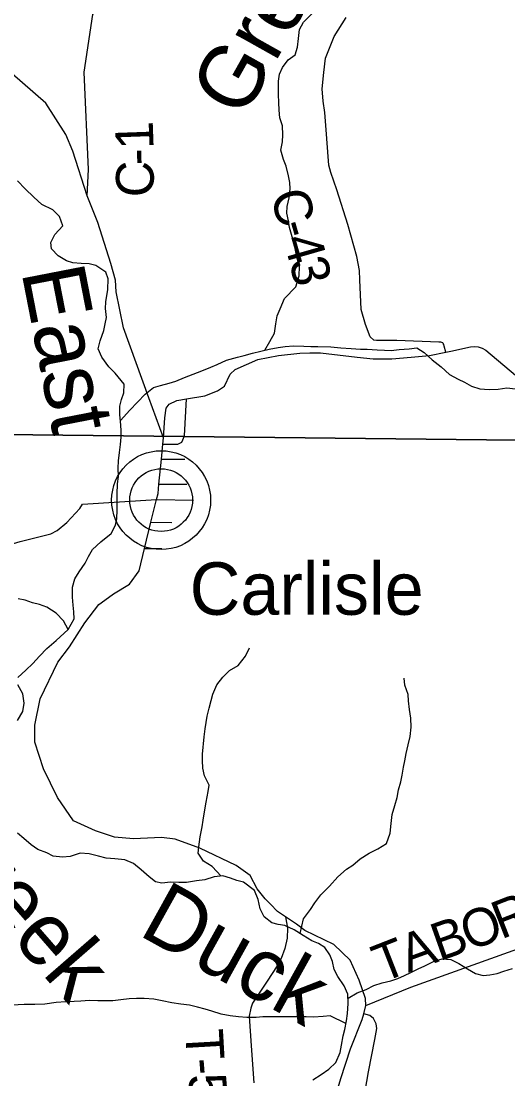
# Model space of a CAD drawing. Extents: x 2043100 to 2470832, y 443715 to 810583.
# Drawn here: x 2286943 to 2290807, y 633122 to 641526 of the extents above; entities that cross this region are included whole.
import ezdxf

# ---------------------------------------------------------------- set-up
doc = ezdxf.new("R2010")
doc.units = 0
for name, color, linetype in [('GM_X_County_Road', 7, 'Continuous'), ('GM_X_County_Road_Text', 7, 'Continuous'), ('GM_X_Major_River', 7, 'Continuous'), ('GM_X_Major_River_Text', 7, 'Continuous'), ('GM_X_Minor_River', 7, 'Continuous'), ('GM_X_Minor_River_Text', 7, 'Continuous'), ('GM_X_Section', 7, 'Continuous'), ('GM_X_State_Route', 7, 'Continuous'), ('GM_X_Township_Road', 7, 'Continuous'), ('GM_X_Township_Road_Text', 7, 'Continuous'), ('GM_X_Township_Subdivision', 7, 'Continuous'), ('GM_X_Unincorporated', 7, 'Continuous'), ('GM_X_Unincorporated_Location', 7, 'Continuous'), ('GM_X_Unincorporated_Text', 7, 'Continuous')]:
    doc.layers.add(name, color=color, linetype=linetype)

msp = doc.modelspace()

# ---------------------------------------------------------------- linework, layer by layer
at = {"layer": 'GM_X_County_Road'}
for points in [[(2287466.2, 640137.7), (2287478.1, 640348.3), (2287444.9, 641121.5), (2287511.6, 641579.3), (2287647.1, 641799.3), (2287668.6, 641842.4)], [(2290315.1, 638896), (2290303, 638942.6), (2290298.3, 638958), (2290294.8, 638964.9), (2290290, 638969.5), (2290282.8, 638972.7), (2290275.2, 638974.5), (2290260.4, 638976), (2289926.2, 638988.4), (2289764.2, 638987.8), (2289744.2, 638991.4), (2289713.7, 639017), (2289676, 639116.5), (2289644, 639234.2), (2289633.4, 639471.7), (2289630.6, 639543.8), (2289607.2, 639655.8), (2289536.2, 639911.5), (2289448.9, 640187), (2289401.3, 640324.7), (2289386.6, 640380.7), (2289379.8, 640450.7), (2289367.7, 640627), (2289355.6, 640801.2), (2289340.6, 640889.2), (2289333.4, 640987.3), (2289345.9, 641117.7), (2289360.5, 641232.1), (2289428.6, 641403.3), (2289522.8, 641554.7)], [(2286710.7, 637324.8), (2286935.8, 637392.2), (2287178.7, 637452.3), (2287230.3, 637479.2), (2287307.2, 637542.6), (2287409.3, 637652.5), (2287430.7, 637686.9), (2288018.2, 637726.2)], [(2289678.9, 633705.8), (2290037.4, 633851.3), (2290990.2, 634192.5)]]:
    msp.add_lwpolyline(points, dxfattribs=at)
at = {"layer": 'GM_X_Major_River'}
for points in [[(2286916.9, 636311.9), (2286980.4, 636370.4), (2287036, 636422.8), (2287089.5, 636481.2), (2287147.1, 636541.7), (2287222.6, 636604.2), (2287315.9, 636692.9)], [(2286915.3, 635969.5), (2286956.7, 636039.9), (2286968.2, 636108), (2286955.8, 636180), (2286917.3, 636251.9)], [(2289324.7, 633155.5), (2289386.4, 633198), (2289441.9, 633252.4), (2289475.3, 633330.7), (2289486.9, 633388.8), (2289500.4, 633463), (2289512, 633515.2), (2289525.5, 633583.3), (2289533.1, 633641.4), (2289538.6, 633719.6), (2289538.1, 633793.7), (2289507.6, 633861.5), (2289457.1, 633935.3), (2289428.8, 633991.2), (2289414.3, 634055.2), (2289394, 634107.1), (2289353.6, 634166.9), (2289303.5, 634196.6), (2289251.4, 634218.3), (2289183.1, 634261.9), (2289110.9, 634305.5), (2289036.7, 634341.1), (2288984.7, 634348.8), (2288932.6, 634362.5), (2288872.4, 634408.1), (2288842, 634472), (2288825.5, 634546), (2288795, 634617.9), (2288708.6, 634685.4), (2288654.6, 634699.1), (2288604.5, 634716.8), (2288544.4, 634734.4), (2288474.5, 634726), (2288402.7, 634703.5), (2288334.9, 634695.1), (2288255, 634682.5), (2288195.1, 634682.2), (2288129.1, 634683.7), (2288059.2, 634677.3), (2288009.2, 634687), (2287959, 634726.7), (2287896.7, 634782.4), (2287836.3, 634834), (2287766.2, 634861.6), (2287688.2, 634871.2), (2287618.2, 634876.7), (2287556.2, 634890.3), (2287484.1, 634909.9), (2287412.2, 634915.4), (2287332.4, 634888.9), (2287270.5, 634882.5), (2287198.5, 634892), (2287146.4, 634917.7), (2287076.3, 634945.3), (2287024.1, 634981), (2286965.7, 635032.7), (2286913.5, 635074.4)], [(2289259, 633115.1), (2289324.7, 633155.5)]]:
    msp.add_lwpolyline(points, dxfattribs=at)
at = {"layer": 'GM_X_Minor_River'}
for points in [[(2289124.6, 639414.1), (2289149.9, 639501.4), (2289153.5, 639575.5), (2289133, 639651.5), (2289122.7, 639707.5), (2289110.4, 639761.5), (2289094.1, 639813.5), (2289073.7, 639887.5), (2289065.4, 639939.5), (2289053.1, 639999.6), (2289054.7, 640053.7), (2289070.3, 640121.8), (2289079.9, 640194), (2289075.6, 640244), (2289065.3, 640298.1), (2289046.9, 640374.1), (2289026.6, 640428), (2289006.2, 640500), (2289017.8, 640566.2), (2289021.4, 640622.3), (2289017, 640694.4), (2288996.7, 640758.3), (2288992.3, 640818.4), (2288990, 640878.5), (2288985.6, 640942.5), (2288987.3, 640996.6), (2288987, 641048.7), (2288994.6, 641104.8), (2289018.3, 641157), (2289063.9, 641219.4), (2289117.6, 641259.8), (2289137.3, 641320), (2289144.9, 641388.1), (2289154.4, 641460.3), (2289184.1, 641518.6), (2289265.6, 641597.2)], [(2287631.8, 639394.5), (2287633.2, 639478.4), (2287616.9, 639532.3), (2287536.6, 639585.9), (2287482.6, 639597.7), (2287418.7, 639599.3), (2287354.7, 639606.9), (2287304.6, 639622.6), (2287236.4, 639660.3), (2287184.2, 639716), (2287179.9, 639766.1), (2287209.5, 639830.4), (2287273, 639900.8), (2287248.6, 639972.8), (2287194.3, 640026.6), (2287108.2, 640068.1), (2287043.9, 640127.8), (2286975.5, 640193.5), (2286915.2, 640257.2)], [(2287315.9, 636692.9), (2287363.2, 636777.3), (2287360.8, 636833.4), (2287356.5, 636885.4), (2287350, 636949.5), (2287351.5, 637029.6), (2287369, 637095.8), (2287402.6, 637150), (2287452.1, 637220.4), (2287477.7, 637272.7), (2287509.3, 637326.9), (2287576.8, 637389.4), (2287658.2, 637456), (2287691.7, 637522.3), (2287703.4, 637572.5), (2287706.9, 637642.6), (2287704.4, 637712.6), (2287706, 637766.7), (2287709.5, 637848.8), (2287715, 637908.9), (2287712.6, 637975), (2287716.2, 638033.1), (2287723.7, 638099.2), (2287731.3, 638161.3), (2287736.9, 638219.4), (2287736.5, 638277.5), (2287732, 638347.6), (2287725.6, 638397.6), (2287727.1, 638465.7), (2287740.8, 638519.8), (2287758.4, 638574), (2287761.9, 638642.1), (2287689.3, 638729.8), (2287639, 638779.5), (2287584.6, 638855.2), (2287554.1, 638923.1), (2287569.7, 638985.3), (2287599.1, 639067.6), (2287610.7, 639121.7), (2287620.3, 639171.8), (2287613.8, 639241.9), (2287615.5, 639296), (2287631.8, 639394.5)], [(2288877.9, 638911.3), (2288916.5, 638979.9), (2288956, 639046.2), (2288965.5, 639120.4), (2288975, 639184.5), (2288998.6, 639240.7), (2289034, 639323), (2289124.6, 639414.1)], [(2287731.1, 638354), (2287805.3, 638436.2), (2287866.8, 638498.6), (2287928.3, 638563.1), (2287993.9, 638615.6), (2288049.7, 638629.9), (2288119.5, 638648.4), (2288171.4, 638664.8), (2288239.1, 638695.2), (2288378.6, 638748.2), (2288448.3, 638776.7), (2288500.1, 638799), (2288573.8, 638831.5), (2288661.6, 638856.1), (2288713.4, 638870.4), (2288781.3, 638886.9), (2288845.1, 638903.3), (2288912.9, 638919.8), (2288982.8, 638932.2), (2289040.7, 638940.6), (2289106.5, 638947.1), (2289188.5, 638943.6), (2289242.5, 638941.9), (2289298.4, 638942.3), (2289402.3, 638938.9), (2289480.3, 638931.4), (2289562.3, 638925.9), (2289638.3, 638920.4), (2289690.2, 638920.7), (2289770.2, 638913.2), (2289828.1, 638911.6), (2289880.1, 638909.9), (2289944, 638916.4), (2290023.9, 638922.9), (2290085.8, 638929.3), (2290142, 638893.6), (2290206.3, 638835.9), (2290276.7, 638778.3), (2290345, 638718.7), (2290413.2, 638681.1), (2290463.3, 638657.4), (2290519.5, 638625.7), (2290585.6, 638604.1), (2290659.6, 638598.5), (2290729.5, 638603), (2290799.4, 638611.4), (2290867.3, 638605.9)], [(2287315.9, 636692.9), (2287279.4, 636760.8), (2287221.1, 636822.5), (2287146.8, 636870.1), (2287088.7, 636889.7), (2287034.6, 636905.4), (2286974.6, 636925), (2286918.5, 636936.7)], [(2288530.4, 634732.8), (2288460, 634808), (2288391.7, 634851.6), (2288349.3, 634915.4), (2288353, 634965.5), (2288364.4, 635045.7), (2288379.8, 635123.9), (2288389.5, 635178), (2288400.9, 635260.2), (2288412.4, 635320.3), (2288427.8, 635404.5), (2288435.5, 635454.6), (2288399, 635530.5), (2288384.6, 635590.4), (2288384.2, 635650.5), (2288383.8, 635700.6), (2288396.8, 635840.8), (2288404.4, 635902.9), (2288419.7, 636003.2), (2288437.2, 636067.4), (2288450.8, 636127.5), (2288464.4, 636179.7), (2288497.9, 636254), (2288543.4, 636314.3), (2288597, 636366.7), (2288666.6, 636407.2), (2288724.1, 636479.7), (2288755.6, 636548)], [(2289157.8, 634277.2), (2289184.2, 634394.1), (2289241.6, 634466.6), (2289275.2, 634520.8), (2289322.7, 634585.2), (2289390.2, 634651.8), (2289457.6, 634728.3), (2289525.1, 634788.8), (2289576.9, 634819.1), (2289634.5, 634869.6), (2289706.1, 634914.1), (2289775.8, 634948.6), (2289843.4, 634993), (2289872.8, 635073.3), (2289880.3, 635151.5), (2289889.8, 635223.6), (2289911.3, 635293.8), (2289928.8, 635358), (2289938.4, 635418.2), (2289957.9, 635482.4), (2289967.5, 635534.5), (2289979.1, 635598.6), (2289988.7, 635648.8), (2290000.3, 635706.9), (2290015.8, 635775.1), (2290031.3, 635841.3), (2290040.8, 635915.4), (2290036.3, 635987.5), (2290025.9, 636055.5), (2290019.4, 636125.5), (2290015, 636175.5), (2289988.5, 636249.5), (2289984.2, 636305.5)], [(2289538.3, 633763.6), (2289611.9, 633806.2), (2289681.7, 633830.6), (2289743.4, 633863), (2289809.2, 633885.5), (2289877, 633901.9), (2289932.8, 633918.3), (2289986.6, 633942.7), (2290038.4, 633967.1), (2290096.2, 633995.5), (2290147.9, 634019.8), (2290221.6, 634056.3), (2290285.4, 634074.8), (2290353.4, 634071.2), (2290417.6, 634037.6), (2290487.8, 633996), (2290550, 633958.3), (2290612.1, 633942.7), (2290664, 633949), (2290723.8, 633959.4), (2290775.7, 633977.8), (2290845.5, 633998.2)], [(2289521.3, 633562.1), (2289395.4, 633622.5), (2289341.5, 633618.2), (2289265.6, 633611.7), (2289205.6, 633615.3), (2288937.9, 633613.6), (2288861.9, 633615.1), (2288808, 633608.8), (2288734.1, 633608.3), (2288670.1, 633613.9), (2288602.1, 633623.5), (2288532.1, 633637), (2288458, 633658.6), (2288403.9, 633676.3), (2288343.8, 633691.9), (2288279.8, 633707.5), (2288211.8, 633715.1), (2288139.8, 633726.7), (2288061.7, 633742.2), (2287997.7, 633753.8), (2287919.7, 633761.3), (2287857.8, 633760.9), (2287801.9, 633758.5), (2287734, 633750.1), (2287670.1, 633741.7), (2287552.2, 633740.9), (2287486.2, 633744.5), (2287418.4, 633738.1), (2287364.4, 633735.7), (2287298.5, 633733.3), (2287220.6, 633728.8), (2287130.8, 633716.2), (2287050.9, 633711.7), (2286966.9, 633713.2), (2286871.1, 633708.5)]]:
    msp.add_lwpolyline(points, dxfattribs=at)
at = {"layer": 'GM_X_Section'}
for points in [[(2285494.3, 643590.2), (2290933.2, 643557.7), (2290892.7, 640243.7), (2290879.4, 638197.4), (2285590.3, 638253.8), (2285414.2, 638253.5)], [(2290879.4, 638197.4), (2290879.2, 634869.9), (2290878.9, 632765), (2285559.9, 632813), (2285590.3, 638253.8)]]:
    msp.add_lwpolyline(points, close=True, dxfattribs=at)
at = {"layer": 'GM_X_State_Route'}
for points in [[(2287957.9, 638532.1), (2287755.8, 639089.2), (2287696.8, 639374.8), (2287692.5, 639469), (2287654.8, 639601.1), (2287551.1, 639926.3), (2287466.2, 640137.7), (2287352.3, 640493.1), (2287299.3, 640624.8), (2287139.7, 640875.5), (2285633.9, 642188.3)], [(2288072.7, 638215.3), (2288083.1, 638375.1), (2288095.5, 638451.6), (2288119, 638483.6), (2288180.5, 638510.7), (2288257.3, 638526.1), (2288402.2, 638550.1), (2288503.1, 638588.2), (2288556.5, 638625.1), (2288602.9, 638720), (2288642.2, 638758.7), (2288821.2, 638837.4), (2288986.1, 638869.8), (2289156.3, 638887.3), (2289236.2, 638891.6), (2289319.2, 638889.6), (2289610.5, 638855), (2289739.2, 638843.9), (2289886.4, 638842.2), (2290039.6, 638856), (2290184.2, 638868.5), (2290315.1, 638896), (2290355.3, 638904.5), (2290511, 638937.7), (2290541.5, 638939.9), (2290571.8, 638937.1), (2290604.4, 638927.7), (2290633.8, 638912.1), (2290868.6, 638713.2)], [(2288072.7, 638215.3), (2287957.9, 638532.1)], [(2287665, 636968), (2287677.3, 636976.7), (2287804, 637053.5), (2287880, 637157.3), (2287921.5, 637334.8), (2287973.2, 637544.3), (2288018.2, 637726.2), (2288030, 637774.1), (2288037, 637846.3), (2288056.3, 638045.4), (2288068, 638166.2), (2288072.7, 638215.3)], [(2288922.2, 634509.7), (2288880.6, 634551.6), (2288816.8, 634630.6), (2288760.4, 634737.8), (2288650.5, 634817.8), (2288363, 634954.4), (2288167, 635026.7), (2288058.5, 635038.5), (2287834.2, 635028), (2287683.6, 635041), (2287534.2, 635092.1), (2287358.1, 635172.8), (2287232, 635356.8), (2287121, 635585.3), (2287052.4, 635796.5), (2287051.6, 635932.9), (2287093.3, 636140.4), (2287235.6, 636432.2), (2287327.3, 636554.4), (2287449.6, 636745.4), (2287558.8, 636892.1), (2287664.6, 636967.6), (2287665, 636968)], [(2289414.2, 632903.4), (2289481.7, 633125.4), (2289559, 633361.7), (2289652, 633593.4), (2289663.1, 633639.7), (2289678.9, 633705.8), (2289676.4, 633759.9), (2289627.8, 633906.7), (2289556.3, 634063.8), (2289425.4, 634189.5), (2289196.5, 634301.2), (2289129.4, 634350), (2289042.9, 634408.8), (2288979.3, 634452.1), (2288922.3, 634509.5), (2288922.2, 634509.7)]]:
    msp.add_lwpolyline(points, dxfattribs=at)
at = {"layer": 'GM_X_Township_Road'}
for points in [[(2289042.9, 634408.8), (2289056.7, 634320.4), (2289056.1, 634240.2), (2289037.5, 634157.8), (2289006.9, 634077.2), (2288975.9, 634020.5), (2288896, 633899), (2288779, 633722.8), (2288765.7, 633682.5), (2288754.8, 633620.2), (2288768.8, 633384.1), (2288791.1, 633089.8), (2288791.2, 633089.4)], [(2289673.4, 632665.9), (2289671.1, 632669.9), (2289654.9, 632683.6), (2289630.5, 632705.3), (2289623.9, 632741.2), (2289623.4, 632769.3), (2289632.9, 632801.5), (2289648.3, 632831.8), (2289657.9, 632856), (2289664.7, 632926.2), (2289675, 633024.5), (2289700.4, 633177.2), (2289751.9, 633434.5), (2289766.4, 633520.9), (2289761.8, 633558.9), (2289741, 633602.6), (2289712.7, 633624.1), (2289663.1, 633639.7)]]:
    msp.add_lwpolyline(points, dxfattribs=at)
at = {"layer": 'GM_X_Township_Subdivision'}
for points in [[(2288068, 638166.2), (2288150.4, 638165.6), (2288186.5, 638164.2), (2288218.2, 638180.8), (2288241.3, 638231.2), (2288257.3, 638526.1)], [(2288056.3, 638045.4), (2288241.7, 638045.4)], [(2288037, 637846.3), (2288259.4, 637846.3)], [(2288018.2, 637726.2), (2288312.3, 637720.3)], [(2287973.2, 637544.3), (2288140.9, 637541.4)], [(2287921.5, 637334.8), (2288060.3, 637334.8)]]:
    msp.add_lwpolyline(points, dxfattribs=at)
at = {"layer": 'GM_X_Unincorporated'}
for radius in [392.8, 249]:
    msp.add_circle((2288054.7, 637720.3), radius, dxfattribs=at)
at = {"layer": 'GM_X_Unincorporated_Location'}
msp.add_line((2288054.7, 637720.3), (2288054.7, 637720.3), dxfattribs=at)

# ---------------------------------------------------------------- texts
at = {"layer": 'GM_X_County_Road_Text'}
for s, rotation, p in [('1', 92.06797, (2287995.6, 640512.5)), ('-', 91.18781, (2287998.3, 640384.3)), ('C', 88.68456, (2287992.6, 640123.7)), ('C', 286.20167, (2288918, 640146.9)), ('-', 286.16092, (2288986.7, 639910.4)), ('4', 286.02832, (2289020.9, 639792.2)), ('3', 283.35466, (2289071, 639618.2)), ('R', 21.35591, (2290754, 634228.7)), ('O', 19.56819, (2290495.7, 634136.7)), ('B', 19.53226, (2290263.3, 634054.2)), ('A', 19.89005, (2290015.5, 633964.6)), ('T', 21.38519, (2289808.5, 633883.5))]:
    msp.add_text(s, height=300, rotation=rotation, dxfattribs=at).set_placement(p)
at = {"layer": 'GM_X_Major_River_Text'}
msp.add_text('Duck', height=499.96, rotation=331.00913, dxfattribs=at).set_placement((2287864.4, 634270.2))
at = {"layer": 'GM_X_Minor_River_Text'}
for s, height, rotation, p in [('Greasy', 499.92, 60.70241, (2288703.7, 640736.9)), ('East', 499.91, 281.00721, (2286944.2, 639536.7)), ('Creek', 499.94, 311.00946, (2286153.8, 635050.9))]:
    msp.add_text(s, height=height, rotation=rotation, dxfattribs=at).set_placement(p)
at = {"layer": 'GM_X_Township_Road_Text'}
for s, rotation, p in [('T', 273.26732, (2288245.1, 633508.8)), ('-', 274.52939, (2288258.3, 633277.5)), ('5', 274.81929, (2288268.2, 633153.1))]:
    msp.add_text(s, height=300, rotation=rotation, dxfattribs=at).set_placement(p)
at = {"layer": 'GM_X_Unincorporated_Text'}
msp.add_text('Carlisle', height=416.67, rotation=0.00001, dxfattribs=at).set_placement((2288281.4, 636809.3))

doc.saveas('drawing.dxf')
